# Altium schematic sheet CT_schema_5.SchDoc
size 611 x 325 mm
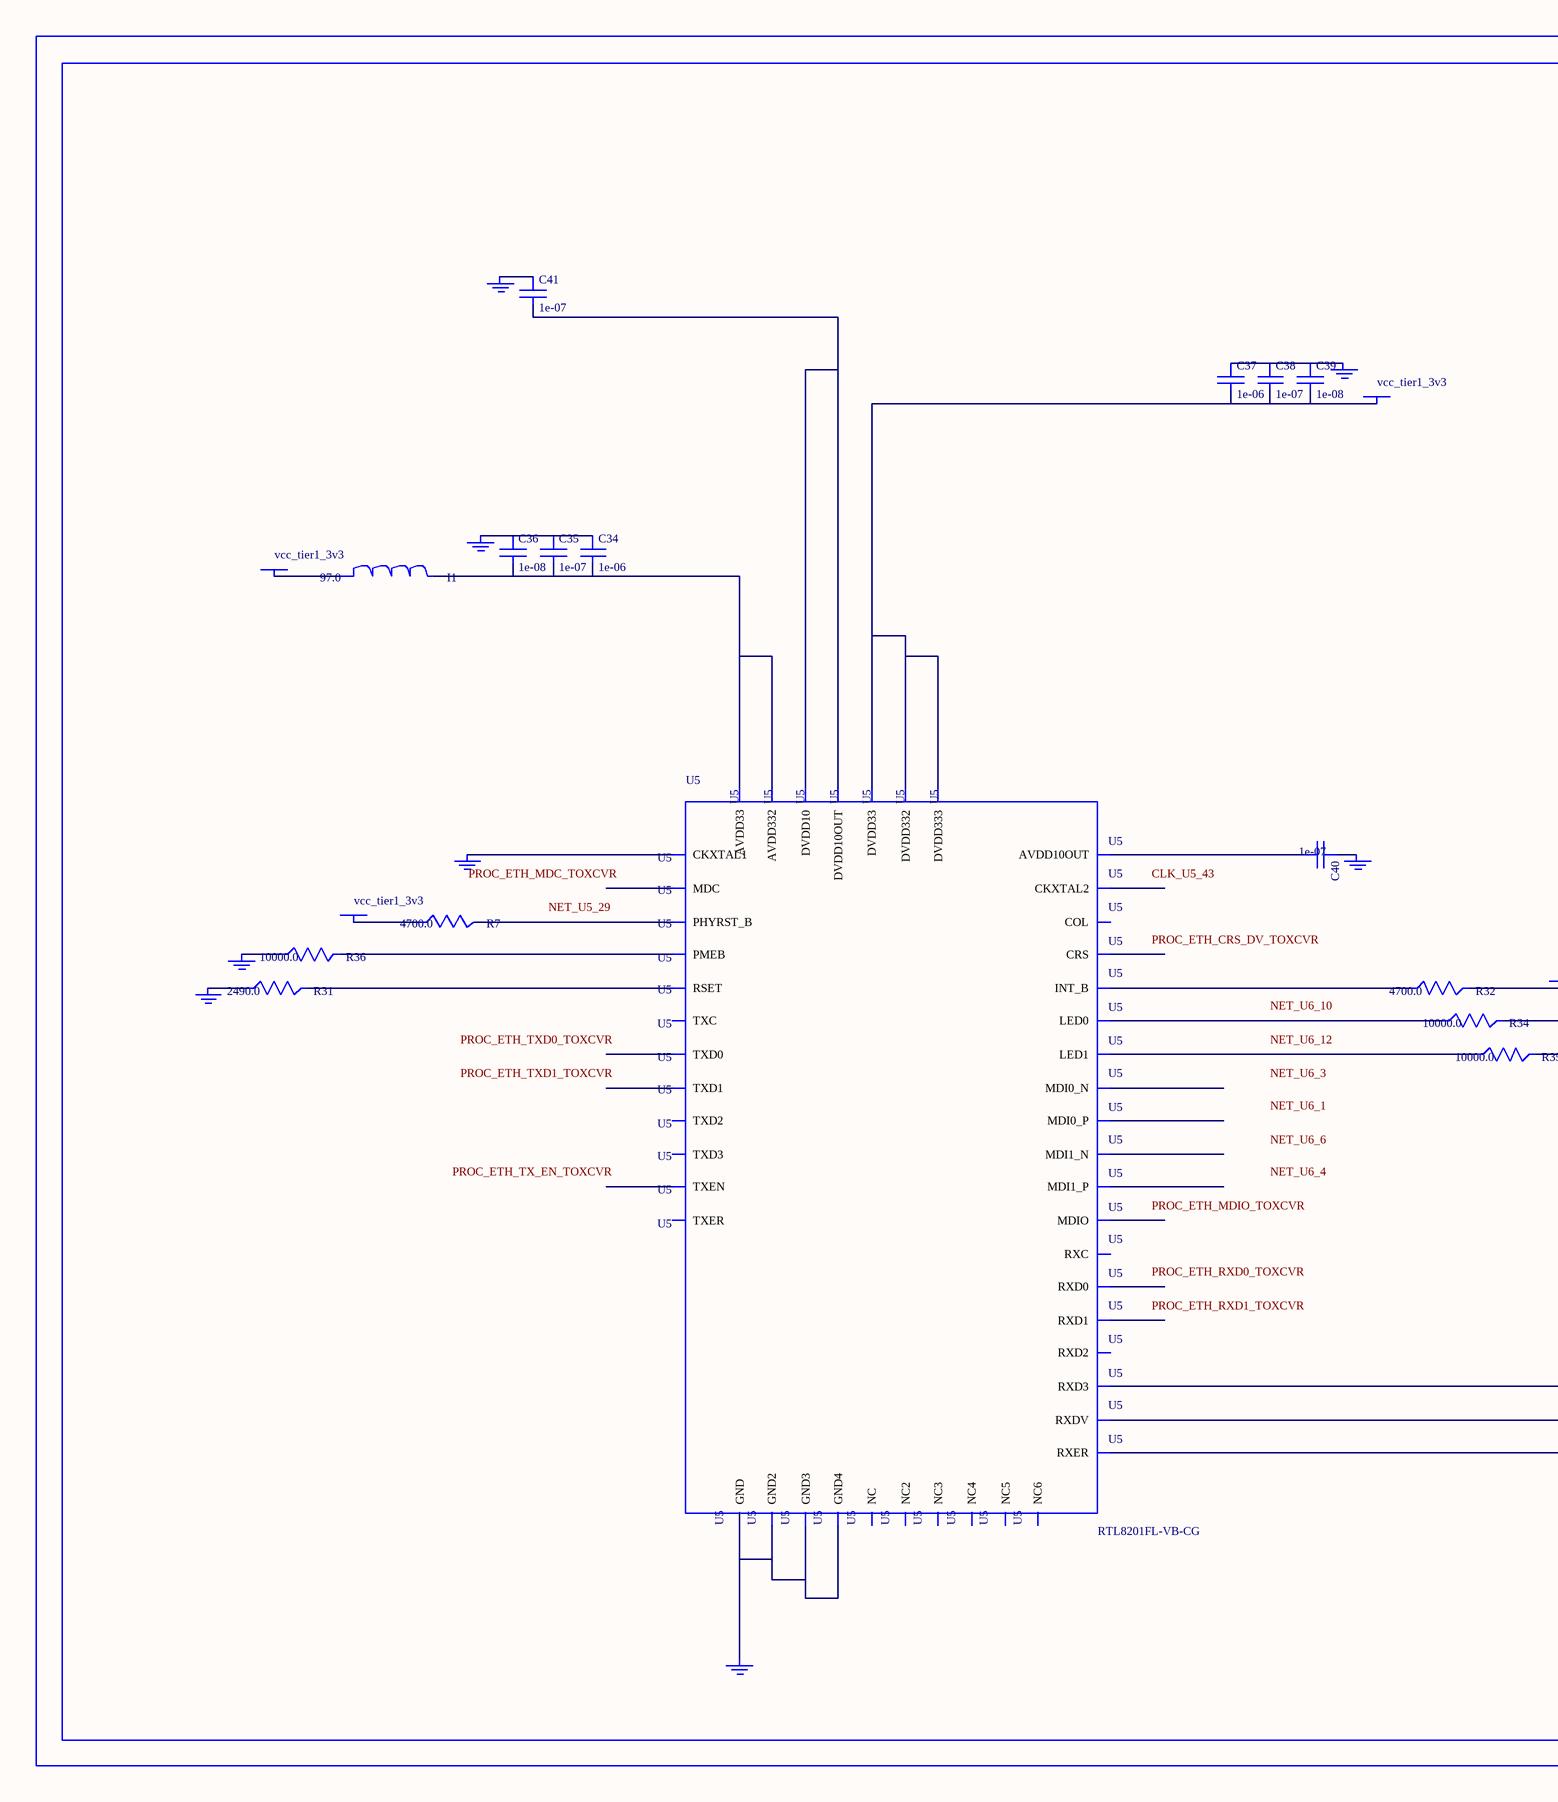
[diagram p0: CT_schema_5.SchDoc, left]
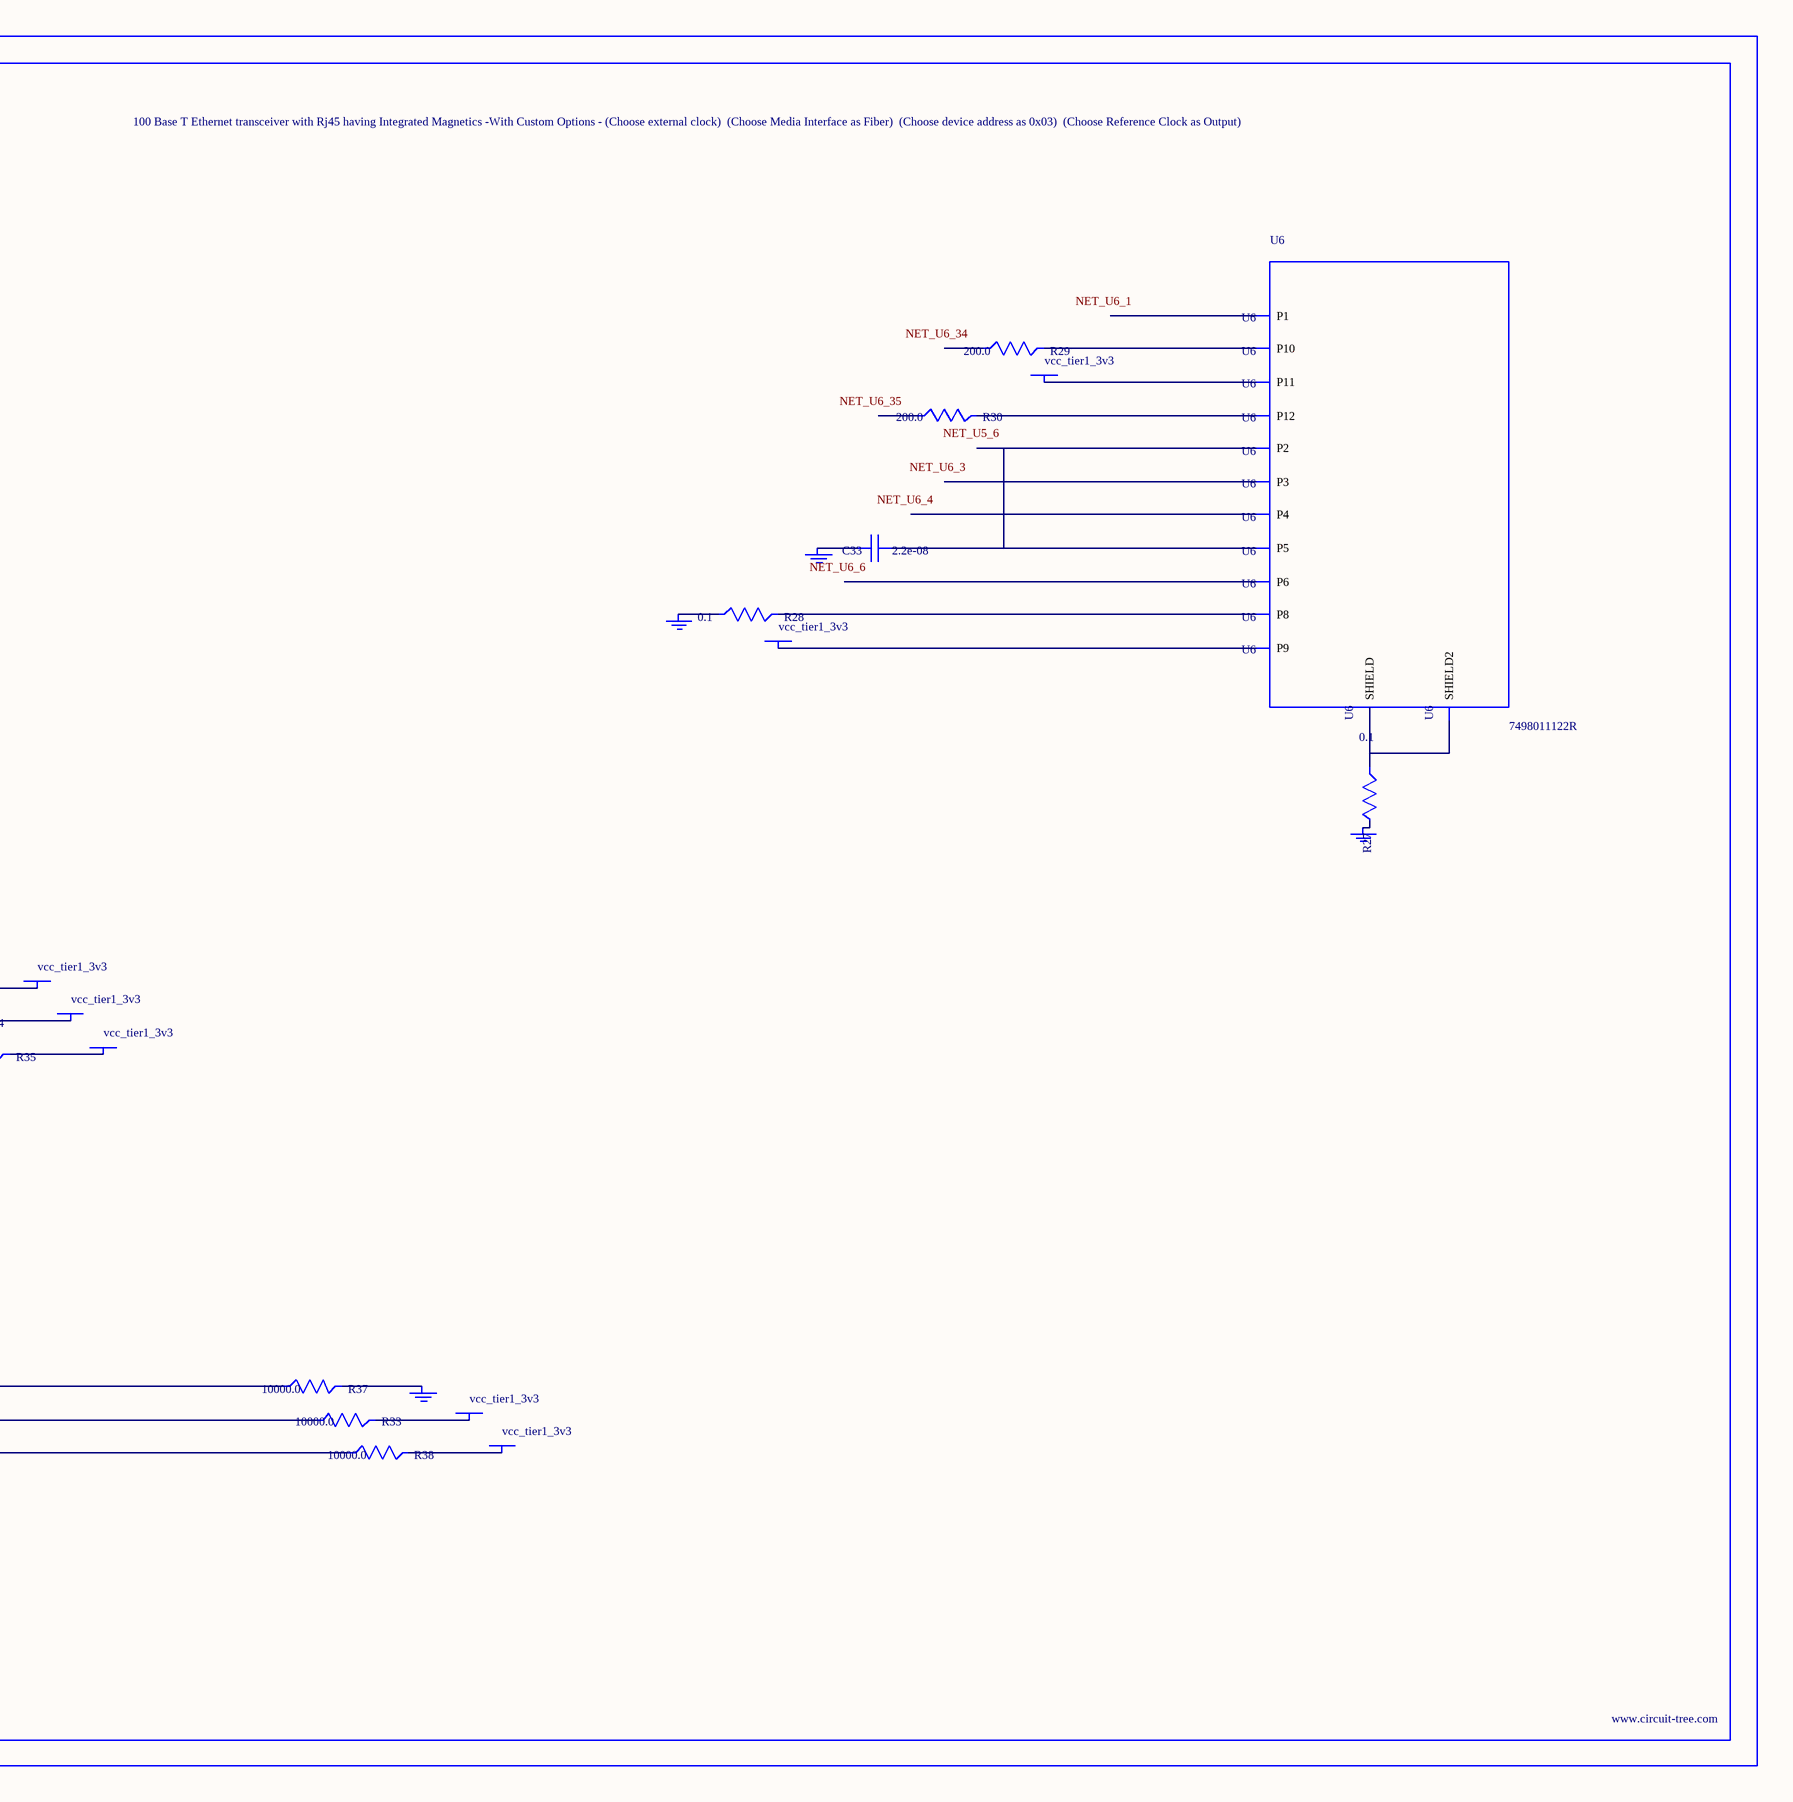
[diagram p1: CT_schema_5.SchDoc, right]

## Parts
BORDER4  (no value)
C33  2.2e-08  [C0402]
C34  1e-06  [C0603]
C35  1e-07  [C0402]
C36  1e-08  [C0402]
C37  1e-06  [C0603]
C38  1e-07  [C0402]
C39  1e-08  [C0402]
C40  1e-07  [C0402]
C41  1e-07  [C0402]
GND_INSTANCE_4_0  (no value)
GND_INSTANCE_4_1  (no value)
GND_INSTANCE_4_2  (no value)
GND_INSTANCE_4_3  (no value)
GND_INSTANCE_4_4  (no value)
GND_INSTANCE_4_5  (no value)
GND_INSTANCE_4_6  (no value)
GND_INSTANCE_4_7  (no value)
GND_INSTANCE_4_8  (no value)
GND_INSTANCE_4_9  (no value)
GND_INSTANCE_4_10  (no value)
GND_INSTANCE_4_11  (no value)
I1  97.0  [R0603]
POWER_INSTANCE_4_0  vcc_tier1_3v3
POWER_INSTANCE_4_1  vcc_tier1_3v3
POWER_INSTANCE_4_2  vcc_tier1_3v3
POWER_INSTANCE_4_3  vcc_tier1_3v3
POWER_INSTANCE_4_4  vcc_tier1_3v3
POWER_INSTANCE_4_5  vcc_tier1_3v3
POWER_INSTANCE_4_6  vcc_tier1_3v3
POWER_INSTANCE_4_7  vcc_tier1_3v3
POWER_INSTANCE_4_8  vcc_tier1_3v3
POWER_INSTANCE_4_9  vcc_tier1_3v3
R7  4700.0  [R0603]
R27  0.1  [R0603]
R28  0.1  [R0603]
R29  200.0  [R0603]
R30  200.0  [R0603]
R31  2490.0  [R0603]
R32  4700.0  [R0603]
R33  10000.0  [R0603]
R34  10000.0  [R0603]
R35  10000.0  [R0603]
R36  10000.0  [R0603]
R37  10000.0  [R0603]
R38  10000.0  [R0603]
U5  RTL8201FL-VB-CG  [RTL8201FL-VB-CG]
U6  7498011122R  [7498011122R]

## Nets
NetC33_1: C33.1 U6.2(P2) U6.5(P5)
NetC33_2: C33.2 GND_INSTANCE_4_9.0(GND)
NetC34_1: C34.1 C35.1 C36.1 GND_INSTANCE_4_0.0(GND)
NetC34_2: C34.2 C35.2 C36.2 I1.2 U5.6(AVDD33) U5.41(AVDD332)
NetC37_1: C37.1 C38.1 C39.1 GND_INSTANCE_4_2.0(GND)
NetC37_2: C37.2 C38.2 C39.2 POWER_INSTANCE_4_2.0(PWR) U5.15(DVDD33) U5.21(DVDD332) U5.37(DVDD333)
NetC40_1: C40.1 GND_INSTANCE_4_7.0(GND)
NetC40_2: C40.2 U5.48(AVDD10OUT)
NetC41_1: C41.1 GND_INSTANCE_4_4.0(GND)
NetC41_2: C41.2 U5.28(DVDD10) U5.40(DVDD10OUT)
NetGND_INSTANCE_4_1_0: GND_INSTANCE_4_1.0(GND) R36.1
NetGND_INSTANCE_4_3_0: GND_INSTANCE_4_3.0(GND) R37.2
NetGND_INSTANCE_4_5_0: GND_INSTANCE_4_5.0(GND) U5.42(CKXTAL1)
NetGND_INSTANCE_4_6_0: GND_INSTANCE_4_6.0(GND) R31.1
NetGND_INSTANCE_4_8_0: GND_INSTANCE_4_8.0(GND) U5.7(GND) U5.20(GND2) U5.33(GND3) U5.47(GND4)
NetGND_INSTANCE_4_10_0: GND_INSTANCE_4_10.0(GND) R28.1
NetGND_INSTANCE_4_11_0: GND_INSTANCE_4_11.0(GND) R27.2
NetI1_1: I1.1 POWER_INSTANCE_4_0.0(PWR)
NetPOWER_INSTANCE_4_1_0: POWER_INSTANCE_4_1.0(PWR) R33.2
NetPOWER_INSTANCE_4_3_0: POWER_INSTANCE_4_3.0(PWR) R32.2
NetPOWER_INSTANCE_4_4_0: POWER_INSTANCE_4_4.0(PWR) R34.2
NetPOWER_INSTANCE_4_5_0: POWER_INSTANCE_4_5.0(PWR) R35.2
NetPOWER_INSTANCE_4_6_0: POWER_INSTANCE_4_6.0(PWR) R38.2
NetPOWER_INSTANCE_4_7_0: POWER_INSTANCE_4_7.0(PWR) R7.1
NetPOWER_INSTANCE_4_8_0: POWER_INSTANCE_4_8.0(PWR) U6.9(P9)
NetPOWER_INSTANCE_4_9_0: POWER_INSTANCE_4_9.0(PWR) U6.11(P11)
NetR7_2: R7.2 U5.29(PHYRST_B)
NetR27_1: R27.1 U6.13(SHIELD) U6.14(SHIELD2)
NetR28_2: R28.2 U6.8(P8)
NetR29_2: R29.2 U6.10(P10)
NetR30_2: R30.2 U6.12(P12)
NetR31_2: R31.2 U5.46(RSET)
NetR32_1: R32.1 U5.32(INT_B)
NetR33_1: R33.1 U5.13(RXDV)
NetR34_1: R34.1 U5.34(LED0)
NetR35_1: R35.1 U5.35(LED1)
NetR36_2: R36.2 U5.10(PMEB)
NetR37_1: R37.1 U5.18(RXD3)
NetR38_1: R38.1 U5.39(RXER)

Not connected (* = marked no-connect by the designer): R29 1; R30 1; U5 1(MDI0_P) 2(MDI0_N) 3(NC) 4(MDI1_P) 5(MDI1_N) 8(NC2) 9(NC3) 11(NC4) 12(TXER) 14(RXD0) 16(RXD1) 17(RXD2) 19(RXC) 22(TXC) 23(TXD0) 24(TXD1) 25(TXD2) 26(TXD3) 27(TXEN) 30(MDC) 31(MDIO) 36(CRS) 38(COL) 43(CKXTAL2) 44(NC5) 45(NC6); U6 1(P1) 3(P3) 4(P4) 6(P6)

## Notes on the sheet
- Labels drawn without touching a wire or pin: CLK_U5_43, NET_U5_6, NET_U5_29, NET_U6_1, NET_U6_3, NET_U6_4, NET_U6_6, NET_U6_10, NET_U6_12, NET_U6_34, NET_U6_35, PROC_ETH_CRS_DV_TOXCVR, PROC_ETH_MDC_TOXCVR, PROC_ETH_MDIO_TOXCVR, PROC_ETH_RXD0_TOXCVR, PROC_ETH_RXD1_TOXCVR, PROC_ETH_TX_EN_TOXCVR, PROC_ETH_TXD0_TOXCVR, PROC_ETH_TXD1_TOXCVR

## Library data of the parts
BORDER4 = BORDER_PAGE4
C33 = C0402C223K3RAC
C34 C37 = C0603C105K3RACTU
C35 C38 C40 C41 = C0402C104K3RACTU
C36 C39 = C0402C103K3RAC
GND_INSTANCE_4_0-GND_INSTANCE_4_11 = GND
I1 = I1
POWER_INSTANCE_4_0-POWER_INSTANCE_4_9 = PWR
R7 R32 = RC0603JR-074K7L
R27 R28 = ERJ-3RSFR10V
R29 R30 = RC0603JR-07200RL
R31 = ERA-3AED2490V
R33-R38 = RC0603JR-0710KL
